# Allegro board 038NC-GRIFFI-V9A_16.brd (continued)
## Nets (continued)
GX1X_3419_17-155: SLOT17.F15
GX1X_3420_17-156: SLOT17.Z15
GX1X_3421_17-157: SLOT17.Z13
GX1X_3422_17-158: SLOT17.A13
GX1X_3423_17-159: SLOT17.B13
GX1X_3424_17-160: SLOT17.C13
GX1X_3425_17-161: SLOT17.D13
GX1X_3426_17-162: SLOT17.E13
GX1X_3427_17-163: SLOT17.F13
GX1X_3428_17-164: SLOT17.A11
GX1X_3429_17-165: SLOT17.B11
GX1X_3430_17-166: SLOT17.C11
GX1X_3431_17-167: SLOT17.D11
GX1X_3432_17-168: SLOT17.E11
GX1X_3433_17-169: SLOT17.F11
GX1X_3434_17-170: SLOT17.Z11
GX1X_3435_17-171: SLOT17.Z9
GX1X_3436_17-172: SLOT17.A9
GX1X_3437_17-173: SLOT17.B9
GX1X_3438_17-174: SLOT17.C9
GX1X_3439_17-175: SLOT17.D9
GX1X_3440_17-176: SLOT17.E9
GX1X_3441_17-177: SLOT17.F9
GX1X_3442_17-178: SLOT17.A7
GX1X_3443_17-179: SLOT17.B7
GX1X_3444_17-180: SLOT17.C7
GX1X_3445_17-181: SLOT17.D7
GX1X_3446_17-182: SLOT17.E7
GX1X_3447_17-183: SLOT17.F7
GX1X_3448_17-184: SLOT17.Z7
GX1X_3449_17-185: SLOT17.Z5
GX1X_3450_17-186: SLOT17.A5
GX1X_3451_17-187: SLOT17.B5
GX1X_3452_17-188: SLOT17.C5
GX1X_3453_17-189: SLOT17.D5
GX1X_3454_17-190: SLOT17.E5
GX1X_3455_17-191: SLOT17.F5
GX1X_3648_19-0: SLOT19.C61
GX1X_3649_19-1: SLOT19.D61
GX1X_3650_19-2: SLOT19.E61
GX1X_3651_19-3: SLOT19.F61
GX1X_3652_19-4: SLOT19.A59
GX1X_3653_19-5: SLOT19.B59
GX1X_3654_19-6: SLOT19.C59
GX1X_3655_19-7: SLOT19.D59
GX1X_3656_19-8: SLOT19.E59
GX1X_3657_19-9: SLOT19.F59
GX1X_3658_19-10: SLOT19.Z59
GX1X_3659_19-11: SLOT19.Z57
GX1X_3660_19-12: SLOT19.A57
GX1X_3661_19-13: SLOT19.B57
GX1X_3662_19-14: SLOT19.C57
GX1X_3663_19-15: SLOT19.D57
GX1X_3664_19-16: SLOT19.E57
GX1X_3665_19-17: SLOT19.F57
GX1X_3666_19-18: SLOT19.A55
GX1X_3667_19-19: SLOT19.B55
GX1X_3668_19-20: SLOT19.C55
GX1X_3669_19-21: SLOT19.D55
GX1X_3670_19-22: SLOT19.E55
GX1X_3671_19-23: SLOT19.F55
GX1X_3672_19-24: SLOT19.Z55
GX1X_3673_19-25: SLOT19.Z53
GX1X_3674_19-26: SLOT19.A53
GX1X_3675_19-27: SLOT19.B53
GX1X_3676_19-28: SLOT19.C53
GX1X_3677_19-29: SLOT19.D53
GX1X_3678_19-30: SLOT19.E53
GX1X_3679_19-31: SLOT19.F53
GX1X_3680_19-32: SLOT19.A51
GX1X_3681_19-33: SLOT19.B51
GX1X_3682_19-34: SLOT19.C51
GX1X_3683_19-35: SLOT19.D51
GX1X_3684_19-36: SLOT19.E51
GX1X_3685_19-37: SLOT19.F51
GX1X_3686_19-38: SLOT19.A49
GX1X_3687_19-39: SLOT19.B49
GX1X_3688_19-40: SLOT19.C49
GX1X_3689_19-41: SLOT19.D49
GX1X_3690_19-42: SLOT19.E49
GX1X_3691_19-43: SLOT19.F49
GX1X_3692_19-44: SLOT19.Z49
GX1X_3693_19-45: SLOT19.Z47
GX1X_3694_19-46: SLOT19.A47
GX1X_3695_19-47: SLOT19.B47
GX1X_3696_19-48: SLOT19.C47
GX1X_3697_19-49: SLOT19.D47
GX1X_3698_19-50: SLOT19.E47
GX1X_3699_19-51: SLOT19.F47
GX1X_3700_19-52: SLOT19.A45
GX1X_3701_19-53: SLOT19.B45
GX1X_3702_19-54: SLOT19.C45
GX1X_3703_19-55: SLOT19.D45
GX1X_3704_19-56: SLOT19.E45
GX1X_3705_19-57: SLOT19.F45
GX1X_3706_19-58: SLOT19.Z45
GX1X_3707_19-59: SLOT19.Z43
GX1X_3708_19-60: SLOT19.A43
GX1X_3709_19-61: SLOT19.B43
GX1X_3710_19-62: SLOT19.C43
GX1X_3711_19-63: SLOT19.D43
GX1X_3712_19-64: SLOT19.A37
GX1X_3713_19-65: SLOT19.B37
GX1X_3714_19-66: SLOT19.C37
GX1X_3715_19-67: SLOT19.D37
GX1X_3716_19-68: SLOT19.E37
GX1X_3717_19-69: SLOT19.F37
GX1X_3718_19-70: SLOT19.A35
GX1X_3719_19-71: SLOT19.B35
GX1X_3720_19-72: SLOT19.C35
GX1X_3721_19-73: SLOT19.D35
GX1X_3722_19-74: SLOT19.E35
GX1X_3723_19-75: SLOT19.F35
GX1X_3724_19-76: SLOT19.Z35
GX1X_3725_19-77: SLOT19.Z33
GX1X_3726_19-78: SLOT19.A33
GX1X_3727_19-79: SLOT19.B33
GX1X_3728_19-80: SLOT19.C33
GX1X_3729_19-81: SLOT19.D33
GX1X_3730_19-82: SLOT19.E33
GX1X_3731_19-83: SLOT19.F33
GX1X_3732_19-84: SLOT19.A31
GX1X_3733_19-85: SLOT19.B31
GX1X_3734_19-86: SLOT19.C31
GX1X_3735_19-87: SLOT19.D31
GX1X_3736_19-88: SLOT19.E31
GX1X_3737_19-89: SLOT19.F31
GX1X_3738_19-90: SLOT19.Z31
GX1X_3739_19-91: SLOT19.Z29
GX1X_3740_19-92: SLOT19.A29
GX1X_3741_19-93: SLOT19.B29
GX1X_3742_19-94: SLOT19.C29
GX1X_3743_19-95: SLOT19.D29
GX1X_3744_19-96: SLOT19.E29
GX1X_3745_19-97: SLOT19.F29
GX1X_3746_19-98: SLOT19.A27
GX1X_3747_19-99: SLOT19.B27
GX1X_3748_19-100: SLOT19.C27
GX1X_3749_19-101: SLOT19.D27
GX1X_3750_19-102: SLOT19.E27
GX1X_3751_19-103: SLOT19.F27
GX1X_3752_19-104: SLOT19.Z27
GX1X_3753_19-105: SLOT19.Z25
GX1X_3754_19-106: SLOT19.A25
GX1X_3755_19-107: SLOT19.B25
GX1X_3756_19-108: SLOT19.C25
GX1X_3757_19-109: SLOT19.D25
GX1X_3758_19-110: SLOT19.E25
GX1X_3759_19-111: SLOT19.F25
GX1X_3760_19-112: SLOT19.A23
GX1X_3761_19-113: SLOT19.B23
GX1X_3762_19-114: SLOT19.C23
GX1X_3763_19-115: SLOT19.D23
GX1X_3764_19-116: SLOT19.E23
GX1X_3765_19-117: SLOT19.F23
GX1X_3766_19-118: SLOT19.Z23
GX1X_3767_19-119: SLOT19.Z21
GX1X_3768_19-120: SLOT19.A21
GX1X_3769_19-121: SLOT19.B21
GX1X_3770_19-122: SLOT19.C21
GX1X_3771_19-123: SLOT19.D21
GX1X_3772_19-124: SLOT19.E21
GX1X_3773_19-125: SLOT19.F21
GX1X_3774_19-126: SLOT19.B19
GX1X_3775_19-127: SLOT19.C19
GX1X_3776_19-128: SLOT19.E43
GX1X_3777_19-129: SLOT19.F43
GX1X_3778_19-130: SLOT19.A41
GX1X_3779_19-131: SLOT19.B41
GX1X_3780_19-132: SLOT19.C41
GX1X_3781_19-133: SLOT19.D41
GX1X_3782_19-134: SLOT19.E41
GX1X_3783_19-135: SLOT19.F41
GX1X_3784_19-136: SLOT19.Z41
GX1X_3785_19-137: SLOT19.Z39
GX1X_3786_19-138: SLOT19.A39
GX1X_3787_19-139: SLOT19.B39
GX1X_3788_19-140: SLOT19.C39
GX1X_3789_19-141: SLOT19.D39
GX1X_3790_19-142: SLOT19.E39
GX1X_3791_19-143: SLOT19.F39
GX1X_3792_19-144: SLOT19.A17
GX1X_3793_19-145: SLOT19.B17
GX1X_3794_19-146: SLOT19.C17
GX1X_3795_19-147: SLOT19.D17
GX1X_3796_19-148: SLOT19.E17
GX1X_3797_19-149: SLOT19.F17
GX1X_3798_19-150: SLOT19.A15
GX1X_3799_19-151: SLOT19.B15
GX1X_3800_19-152: SLOT19.C15
GX1X_3801_19-153: SLOT19.D15
GX1X_3802_19-154: SLOT19.E15
GX1X_3803_19-155: SLOT19.F15
GX1X_3804_19-156: SLOT19.Z15
GX1X_3805_19-157: SLOT19.Z13
GX1X_3806_19-158: SLOT19.A13
GX1X_3807_19-159: SLOT19.B13
GX1X_3808_19-160: SLOT19.C13
GX1X_3809_19-161: SLOT19.D13
GX1X_3810_19-162: SLOT19.E13
GX1X_3811_19-163: SLOT19.F13
GX1X_3812_19-164: SLOT19.A11
GX1X_3813_19-165: SLOT19.B11
GX1X_3814_19-166: SLOT19.C11
GX1X_3815_19-167: SLOT19.D11
GX1X_3816_19-168: SLOT19.E11
GX1X_3817_19-169: SLOT19.F11
GX1X_3818_19-170: SLOT19.Z11
GX1X_3819_19-171: SLOT19.Z9
GX1X_3820_19-172: SLOT19.A9
GX1X_3821_19-173: SLOT19.B9
GX1X_3822_19-174: SLOT19.C9
GX1X_3823_19-175: SLOT19.D9
GX1X_3824_19-176: SLOT19.E9
GX1X_3825_19-177: SLOT19.F9
GX1X_3826_19-178: SLOT19.A7
GX1X_3827_19-179: SLOT19.B7
GX1X_3828_19-180: SLOT19.C7
GX1X_3829_19-181: SLOT19.D7
GX1X_3830_19-182: SLOT19.E7
GX1X_3831_19-183: SLOT19.F7
GX1X_3832_19-184: SLOT19.Z7
GX1X_3833_19-185: SLOT19.Z5
GX1X_3834_19-186: SLOT19.A5
GX1X_3835_19-187: SLOT19.B5
GX1X_3836_19-188: SLOT19.C5
GX1X_3837_19-189: SLOT19.D5
GX1X_3838_19-190: SLOT19.E5
GX1X_3839_19-191: SLOT19.F5
HDVI_721_10-CH1BP: SLOT10.B35
HDVI_721_10-CH1F: SLOT10.F33 SLOT10.F35 UNK8K10.2
HDVI_721_10-CH1GS: SLOT10.A33 SLOT10.A35 UNK8SH9.1
HDVI_721_10-CH1S: SLOT10.C33 SLOT10.C35 UNK8K10.7
HDVI_722_10-CH2BP: SLOT10.B33
HDVI_723_10-CH3BP: SLOT10.B31
HDVI_723_10-CH3F: SITE8.F25(VSYS_F) SLOT10.F29 SLOT10.F31 UNK8CS25.1 UNK8K2.3 UNK8TP_VSYS_F.1
HDVI_723_10-CH3GS: SLOT10.A29 SLOT10.A31 UNK8SH7.2
HDVI_723_10-CH3S: SITE8.S25(VSYS_S) SLOT10.C29 SLOT10.C31 UNK8TP_VSYS_S.1
HDVI_724_10-CH4BP: SLOT10.B29
HDVI_725_10-CH5BP: SLOT10.B27
HDVI_725_10-CH5F: SITE8.F5(LSOUT1 / ILIM1_F) SLOT10.F27 UNK8CS5.2 UNK8K8.3 UNK8SH36.2 UNK8TP_LSOUT1_F.1
HDVI_725_10-CH5GS: SLOT10.A27 UNK8SH32.1
HDVI_725_10-CH5S: SITE8.S5(LSOUT1 / ILIM1_S) SLOT10.C27 UNK8TP_LSOUT1_S.1
HDVI_726_10-CH6BP: SLOT10.B25
HDVI_726_10-CH6F: SLOT10.F25 UNK8K13.4 UNK8TP_NPG/ATB1_F.1
HDVI_726_10-CH6GS: SLOT10.A25 UNK8SH16.1
HDVI_726_10-CH6S: SLOT10.C25 UNK8K13.5 UNK8TP_NPG/ATB1_S.1
HDVI_727_10-CH7BP: SLOT10.B23
HDVI_727_10-CH7F: SLOT10.F23 UNK8K14.4 UNK8TP_NCHG/ATB0_F.1
HDVI_727_10-CH7GS: SLOT10.A23 UNK8SH14.1
HDVI_727_10-CH7S: SLOT10.C23 UNK8K14.5
HDVI_728_10-CH8BP: SLOT10.B21
HDVI_728_10-CH8F: SITE8.F19(LSOUT2 / SUSPEND_F) SLOT10.F21 UNK8CS19.1 UNK8K8.6 UNK8SH38.2 UNK8TP_LSOUT2/SUSPEND_F.1
HDVI_728_10-CH8GS: SLOT10.A21 UNK8SH30.2
HDVI_728_10-CH8S: SITE8.S19(LSOUT2 / SUSPEND_S) SLOT10.C21 UNK8TP_LSOUT2/SUSPEND1_S.1
HDVI_729_10-CH9BP: SLOT10.D37
HDVI_729_10-CH9F: SLOT10.E35 SLOT10.F37 UNK6K10.2
HDVI_729_10-CH9GS: SLOT10.B37 SLOT10.C37 UNK6SH9.1
HDVI_729_10-CH9S: SLOT10.E33 SLOT10.E37 UNK6K10.7
HDVI_730_10-CH10BP: SLOT10.D33
HDVI_731_10-CH11BP: SLOT10.D29
HDVI_731_10-CH11F: SITE6.F25(VSYS_F) SLOT10.E27 SLOT10.E31 UNK6CS25.1 UNK6K2.3 UNK6TP_VSYS_F.1
HDVI_731_10-CH11GS: SLOT10.A37 SLOT10.B19 UNK6SH7.2
HDVI_731_10-CH11S: SITE6.S25(VSYS_S) SLOT10.E25 SLOT10.E29 UNK6TP_VSYS_S.1
HDVI_732_10-CH12BP: SLOT10.D25
HDVI_733_10-CH13BP: SLOT10.D21
HDVI_733_10-CH13F: SITE6.F5(LSOUT1 / ILIM1_F) SLOT10.E23 UNK6CS5.2 UNK6K8.3 UNK6SH36.2 UNK6TP_LSOUT1_F.1
HDVI_733_10-CH13GS: SLOT10.A19 UNK6SH32.1
HDVI_733_10-CH13S: SITE6.S5(LSOUT1 / ILIM1_S) SLOT10.E21 UNK6TP_LSOUT1_S.1
HDVI_734_10-CH14BP: SLOT10.D19
HDVI_734_10-CH14F: SLOT10.F19 UNK6K13.4 UNK6TP_NPG/ATB1_F.1
HDVI_734_10-CH14GS: SLOT10.C19 UNK6SH16.1
HDVI_734_10-CH14S: SLOT10.E19 UNK6K13.5 UNK6TP_NPG/ATB1_S.1
HDVI_735_10-CH15BP: SLOT10.D17
HDVI_735_10-CH15F: SLOT10.F17 UNK6K14.4 UNK6TP_NCHG/ATB0_F.1
HDVI_735_10-CH15GS: SLOT10.A17 UNK6SH14.1
HDVI_735_10-CH15S: SLOT10.E17 UNK6K14.5
HDVI_736_10-CH16BP: SLOT10.C17
HDVI_736_10-CH16F: SITE6.F19(LSOUT2 / SUSPEND_F) SLOT10.E15 UNK6CS19.1 UNK6K8.6 UNK6SH38.2 UNK6TP_LSOUT2/SUSPEND_F.1
HDVI_736_10-CH16GS: SLOT10.B17 UNK6SH30.2
HDVI_736_10-CH16S: SITE6.S19(LSOUT2 / SUSPEND_S) SLOT10.D15 UNK6TP_LSOUT2/SUSPEND1_S.1
HDVI_737_10-CH17BP: SLOT10.B15
HDVI_737_10-CH17F: SLOT10.F13 SLOT10.F15 UNK2K10.2
HDVI_737_10-CH17GS: SLOT10.A13 SLOT10.A15 UNK2SH9.1
HDVI_737_10-CH17S: SLOT10.C15 SLOT10.E13 UNK2K10.7
HDVI_738_10-CH18BP: SLOT10.D13
HDVI_739_10-CH19BP: SLOT10.D11
HDVI_739_10-CH19F: SITE2.F25(VSYS_F) SLOT10.E9 SLOT10.F11 UNK2CS25.1 UNK2K2.3 UNK2TP_VSYS_F.1
HDVI_739_10-CH19GS: SLOT10.B13 SLOT10.C13 UNK2SH7.2
HDVI_739_10-CH19S: SITE2.S25(VSYS_S) SLOT10.D9 SLOT10.E11 UNK2TP_VSYS_S.1
HDVI_740_10-CH20BP: SLOT10.C11
HDVI_741_10-CH21BP: SLOT10.B9
HDVI_741_10-CH21F: SITE2.F5(LSOUT1 / ILIM1_F) SLOT10.F9 UNK2CS5.2 UNK2K8.3 UNK2SH36.2 UNK2TP_LSOUT1_F.1
HDVI_741_10-CH21GS: SLOT10.B11 UNK2SH32.1
HDVI_741_10-CH21S: SITE2.S5(LSOUT1 / ILIM1_S) SLOT10.C9 UNK2TP_LSOUT1_S.1
HDVI_742_10-CH22BP: SLOT10.D7
HDVI_742_10-CH22F: SLOT10.F7 UNK2K13.4 UNK2TP_NPG/ATB1_F.1
HDVI_742_10-CH22GS: SLOT10.A11 UNK2SH16.1
HDVI_742_10-CH22S: SLOT10.E7 UNK2K13.5 UNK2TP_NPG/ATB1_S.1
HDVI_743_10-CH23BP: SLOT10.D5
HDVI_743_10-CH23F: SLOT10.F5 UNK2K14.4 UNK2TP_NCHG/ATB0_F.1
HDVI_743_10-CH23GS: SLOT10.A9 UNK2SH14.1
HDVI_743_10-CH23S: SLOT10.E5 UNK2K14.5
HDVI_744_10-CH24BP: SLOT10.D3
HDVI_744_10-CH24F: SITE2.F19(LSOUT2 / SUSPEND_F) SLOT10.F3 UNK2CS19.1 UNK2K8.6 UNK2SH38.2 UNK2TP_LSOUT2/SUSPEND_F.1
HDVI_744_10-CH24GS: SLOT10.A7 UNK2SH30.2
HDVI_744_10-CH24S: SITE2.S19(LSOUT2 / SUSPEND_S) SLOT10.E3 UNK2TP_LSOUT2/SUSPEND1_S.1
HDVI_745_10-CH25BP: SLOT10.D1
HDVI_745_10-CH25F: SLOT10.F1
HDVI_745_10-CH25GS: SLOT10.B7
HDVI_745_10-CH25S: SLOT10.E1
HDVI_746_10-CH26BP: SLOT10.C3
HDVI_746_10-CH26F: SLOT10.G4
HDVI_746_10-CH26GS: SLOT10.C7
HDVI_746_10-CH26S: SLOT10.C1
HDVI_747_10-CH27BP: SLOT10.D2
HDVI_747_10-CH27F: SLOT10.F2
HDVI_747_10-CH27GS: SLOT10.C5
HDVI_747_10-CH27S: SLOT10.C4
HDVI_748_10-CH28BP: SLOT10.B3
HDVI_748_10-CH28F: SLOT10.A4
HDVI_748_10-CH28GS: SLOT10.B5
HDVI_748_10-CH28S: SLOT10.B1
HDVI_749_10-CH29BP: SLOT10.A3
HDVI_749_10-CH29F: SLOT10.B2
HDVI_749_10-CH29GS: SLOT10.A5
HDVI_749_10-CH29S: SLOT10.A1
HDVI_750_10-CH30BP: SLOT10.A60
HDVI_750_10-CH30F: SLOT10.B62
HDVI_750_10-CH30GS: SLOT10.B58
HDVI_750_10-CH30S: SLOT10.A61
HDVI_751_10-CH31BP: SLOT10.A59
HDVI_751_10-CH31F: SLOT10.C62
HDVI_751_10-CH31GS: SLOT10.A57
HDVI_751_10-CH31S: SLOT10.B61
HDVI_752_10-CH32BP: SLOT10.E60
HDVI_752_10-CH32F: SLOT10.F62
HDVI_752_10-CH32GS: SLOT10.C60
HDVI_752_10-CH32S: SLOT10.F61
HDVI_753_10-CH33BP: SLOT10.D61
HDVI_753_10-CH33F: SLOT10.E62 SLOT10.F59 UNK16K10.2
HDVI_753_10-CH33GS: SLOT10.B59 SLOT10.C61 UNK16SH9.1
HDVI_753_10-CH33S: SLOT10.D59 SLOT10.E61 UNK16K10.7
HDVI_754_10-CH34BP: SLOT10.C59
HDVI_755_10-CH35BP: SLOT10.F58
HDVI_755_10-CH35F: SITE16.F25(VSYS_F) SLOT10.E57 SLOT10.G60 UNK16CS25.1 UNK16K2.3 UNK16TP_VSYS_F.1
HDVI_755_10-CH35GS: SLOT10.B57 SLOT10.D58 UNK16SH7.2
HDVI_755_10-CH35S: SITE16.S25(VSYS_S) SLOT10.D57 SLOT10.E59 UNK16TP_VSYS_S.1
HDVI_756_10-CH36BP: SLOT10.C57
HDVI_757_10-CH37BP: SLOT10.E56
HDVI_757_10-CH37F: SITE16.F5(LSOUT1 / ILIM1_F) SLOT10.F57 UNK16CS5.2 UNK16K8.3 UNK16SH36.2 UNK16TP_LSOUT1_F.1
HDVI_757_10-CH37GS: SLOT10.C56 UNK16SH32.1
HDVI_757_10-CH37S: SITE16.S5(LSOUT1 / ILIM1_S) SLOT10.G56 UNK16TP_LSOUT1_S.1
HDVI_758_10-CH38BP: SLOT10.D55
HDVI_758_10-CH38F: SLOT10.F55 UNK16K13.4 UNK16TP_NPG/ATB1_F.1
HDVI_758_10-CH38GS: SLOT10.B55 UNK16SH16.1
HDVI_758_10-CH38S: SLOT10.E55 UNK16K13.5 UNK16TP_NPG/ATB1_S.1
HDVI_759_10-CH39BP: SLOT10.B54
HDVI_759_10-CH39F: SLOT10.E52 UNK16K14.4 UNK16TP_NCHG/ATB0_F.1
HDVI_759_10-CH39GS: SLOT10.A55 UNK16SH14.1
HDVI_759_10-CH39S: SLOT10.C55 UNK16K14.5
HDVI_760_10-CH40BP: SLOT10.D54
HDVI_760_10-CH40F: SITE16.F19(LSOUT2 / SUSPEND_F) SLOT10.G52 UNK16CS19.1 UNK16K8.6 UNK16SH38.2 UNK16TP_LSOUT2/SUSPEND_F.1
HDVI_760_10-CH40GS: SLOT10.A56 UNK16SH30.2
HDVI_760_10-CH40S: SITE16.S19(LSOUT2 / SUSPEND_S) SLOT10.F54 UNK16TP_LSOUT2/SUSPEND1_S.1
HDVI_761_10-CH41BP: SLOT10.B53
HDVI_761_10-CH41F: SLOT10.F51 SLOT10.F53 UNK14K10.2
HDVI_761_10-CH41GS: SLOT10.A52 SLOT10.A53 UNK14SH9.1
HDVI_761_10-CH41S: SLOT10.C53 SLOT10.E53 UNK14K10.7
HDVI_762_10-CH42BP: SLOT10.D53
HDVI_763_10-CH43BP: SLOT10.C51
HDVI_763_10-CH43F: SITE14.F25(VSYS_F) SLOT10.E51 SLOT10.F49 UNK14CS25.1 UNK14K2.3 UNK14TP_VSYS_F.1
HDVI_763_10-CH43GS: SLOT10.A51 SLOT10.C52 UNK14SH7.2
HDVI_763_10-CH43S: SITE14.S25(VSYS_S) SLOT10.D51 SLOT10.F50 UNK14TP_VSYS_S.1
HDVI_764_10-CH44BP: SLOT10.D50
HDVI_765_10-CH45BP: SLOT10.B50
HDVI_765_10-CH45F: SITE14.F5(LSOUT1 / ILIM1_F) SLOT10.E49 UNK14CS5.2 UNK14K8.3 UNK14SH36.2 UNK14TP_LSOUT1_F.1
HDVI_765_10-CH45GS: SLOT10.B51 UNK14SH32.1
HDVI_765_10-CH45S: SITE14.S5(LSOUT1 / ILIM1_S) SLOT10.D49 UNK14TP_LSOUT1_S.1
HDVI_766_10-CH46BP: SLOT10.B49
HDVI_766_10-CH46F: SLOT10.G48 UNK14K13.4 UNK14TP_NPG/ATB1_F.1
HDVI_766_10-CH46GS: SLOT10.A49 UNK14SH16.1
HDVI_766_10-CH46S: SLOT10.C49 UNK14K13.5 UNK14TP_NPG/ATB1_S.1
HDVI_767_10-CH47BP: SLOT10.D47
HDVI_767_10-CH47F: SLOT10.F47 UNK14K14.4 UNK14TP_NCHG/ATB0_F.1
HDVI_767_10-CH47GS: SLOT10.A48 UNK14SH14.1
HDVI_767_10-CH47S: SLOT10.E47 UNK14K14.5
HDVI_768_10-CH48BP: SLOT10.C45
HDVI_768_10-CH48F: SITE14.F19(LSOUT2 / SUSPEND_F) SLOT10.F45 UNK14CS19.1 UNK14K8.6 UNK14SH38.2 UNK14TP_LSOUT2/SUSPEND_F.1
HDVI_768_10-CH48GS: SLOT10.C48 UNK14SH30.2
HDVI_768_10-CH48S: SITE14.S19(LSOUT2 / SUSPEND_S) SLOT10.D46 UNK14TP_LSOUT2/SUSPEND1_S.1
HDVI_769_10-CH49BP: SLOT10.C47
HDVI_769_10-CH49F: SLOT10.F46 SLOT10.G44 UNK12K10.2
HDVI_769_10-CH49GS: SLOT10.B47 SLOT10.E48 UNK12SH9.1
HDVI_769_10-CH49S: SLOT10.B45 SLOT10.E45 UNK12K10.7
HDVI_770_10-CH50BP: SLOT10.B46
HDVI_771_10-CH51BP: SLOT10.D45
HDVI_771_10-CH51F: SITE12.F25(VSYS_F) SLOT10.F41 SLOT10.F43 UNK12CS25.1 UNK12K2.3 UNK12TP_VSYS_F.1
HDVI_771_10-CH51GS: SLOT10.A45 SLOT10.A47 UNK12SH7.2
HDVI_771_10-CH51S: SITE12.S25(VSYS_S) SLOT10.E43 SLOT10.F42 UNK12TP_VSYS_S.1
HDVI_772_10-CH52BP: SLOT10.D43
HDVI_773_10-CH53BP: SLOT10.D42
HDVI_773_10-CH53F: SITE12.F5(LSOUT1 / ILIM1_F) SLOT10.G40 UNK12CS5.2 UNK12K8.3 UNK12SH36.2 UNK12TP_LSOUT1_F.1
HDVI_773_10-CH53GS: SLOT10.A44 UNK12SH32.1
HDVI_773_10-CH53S: SITE12.S5(LSOUT1 / ILIM1_S) SLOT10.E41 UNK12TP_LSOUT1_S.1
HDVI_774_10-CH54BP: SLOT10.C41
HDVI_774_10-CH54F: SLOT10.F39 UNK12K13.4 UNK12TP_NPG/ATB1_F.1
HDVI_774_10-CH54GS: SLOT10.C44 UNK12SH16.1
HDVI_774_10-CH54S: SLOT10.D41 UNK12K13.5 UNK12TP_NPG/ATB1_S.1
HDVI_775_10-CH55BP: SLOT10.B41
HDVI_775_10-CH55F: SLOT10.F38 UNK12K14.4 UNK12TP_NCHG/ATB0_F.1
HDVI_775_10-CH55GS: SLOT10.E44 UNK12SH14.1
HDVI_775_10-CH55S: SLOT10.B39 UNK12K14.5
HDVI_776_10-CH56BP: SLOT10.C39
HDVI_776_10-CH56F: SITE12.F19(LSOUT2 / SUSPEND_F) SLOT10.E39 UNK12CS19.1 UNK12K8.6 UNK12SH38.2 UNK12TP_LSOUT2/SUSPEND_F.1
HDVI_776_10-CH56GS: SLOT10.C43 UNK12SH30.2
HDVI_776_10-CH56S: SITE12.S19(LSOUT2 / SUSPEND_S) SLOT10.D39 UNK12TP_LSOUT2/SUSPEND1_S.1
HDVI_777_10-CH57BP: SLOT10.A41
HDVI_777_10-CH57F: SLOT10.C40 SLOT10.E40 UNK10K10.2
HDVI_777_10-CH57GS: SLOT10.A43 SLOT10.B43 UNK10SH9.1
HDVI_777_10-CH57S: SLOT10.A39 SLOT10.A40 UNK10K10.7
HDVI_778_10-CH58BP: SLOT10.B42
HDVI_779_10-CH59BP: SLOT10.C36
HDVI_779_10-CH59F: SITE10.F25(VSYS_F) SLOT10.G32 SLOT10.G36 UNK10CS25.1 UNK10K2.3 UNK10TP_VSYS_F.1
HDVI_779_10-CH59GS: SLOT10.B38 SLOT10.D38 UNK10SH7.2
HDVI_779_10-CH59S: SITE10.S25(VSYS_S) SLOT10.E32 SLOT10.E36 UNK10TP_VSYS_S.1
HDVI_780_10-CH60BP: SLOT10.D34
HDVI_781_10-CH61BP: SLOT10.E24
HDVI_781_10-CH61F: SITE10.F5(LSOUT1 / ILIM1_F) SLOT10.E28 UNK10CS5.2 UNK10K8.3 UNK10SH36.2 UNK10TP_LSOUT1_F.1
HDVI_781_10-CH61GS: SLOT10.A36 UNK10SH32.1
HDVI_781_10-CH61S: SITE10.S5(LSOUT1 / ILIM1_S) SLOT10.F26 UNK10TP_LSOUT1_S.1
HDVI_782_10-CH62BP: SLOT10.F18
HDVI_782_10-CH62F: SLOT10.G20 UNK10K13.4 UNK10TP_NPG/ATB1_F.1
HDVI_782_10-CH62GS: SLOT10.B10 UNK10SH16.1
HDVI_782_10-CH62S: SLOT10.E16 UNK10K13.5 UNK10TP_NPG/ATB1_S.1
HDVI_783_10-CH63BP: SLOT10.E12
HDVI_783_10-CH63F: SLOT10.F14 UNK10K14.4 UNK10TP_NCHG/ATB0_F.1
HDVI_783_10-CH63GS: SLOT10.A8 UNK10SH14.1
HDVI_783_10-CH63S: SLOT10.D10 UNK10K14.5
HDVI_784_10-CH64BP: SLOT10.E8
HDVI_784_10-CH64F: SITE10.F19(LSOUT2 / SUSPEND_F) SLOT10.G8 UNK10CS19.1 UNK10K8.6 UNK10SH38.2 UNK10TP_LSOUT2/SUSPEND_F.1
HDVI_784_10-CH64GS: SLOT10.C8 UNK10SH30.2
HDVI_784_10-CH64S: SITE10.S19(LSOUT2 / SUSPEND_S) SLOT10.F6 UNK10TP_LSOUT2/SUSPEND1_S.1
HDVI_785_10-CH65BP: SLOT10.B34
HDVI_785_10-CH65F: SLOT10.F30 SLOT10.F34 UNK4K10.2
HDVI_785_10-CH65GS: SLOT10.A32 SLOT10.B30 UNK4SH9.1
HDVI_785_10-CH65S: SLOT10.C28 SLOT10.C32 UNK4K10.7
HDVI_786_10-CH66BP: SLOT10.D30
HDVI_787_10-CH67BP: SLOT10.B26
HDVI_787_10-CH67F: SITE4.F25(VSYS_F) SLOT10.G24 SLOT10.G28 UNK4CS25.1 UNK4K2.3 UNK4TP_VSYS_F.1
HDVI_787_10-CH67GS: SLOT10.A24 SLOT10.A28 UNK4SH7.2
HDVI_787_10-CH67S: SITE4.S25(VSYS_S) SLOT10.B22 SLOT10.D26 UNK4TP_VSYS_S.1
HDVI_788_10-CH68BP: SLOT10.C24
HDVI_789_10-CH69BP: SLOT10.C20
HDVI_789_10-CH69F: SITE4.F5(LSOUT1 / ILIM1_F) SLOT10.F22 UNK4CS5.2 UNK4K8.3 UNK4SH36.2 UNK4TP_LSOUT1_F.1
HDVI_789_10-CH69GS: SLOT10.A20 UNK4SH32.1
HDVI_789_10-CH69S: SITE4.S5(LSOUT1 / ILIM1_S) SLOT10.D22 UNK4TP_LSOUT1_S.1
HDVI_790_10-CH70BP: SLOT10.D18
HDVI_790_10-CH70F: SLOT10.G16 UNK4K13.4 UNK4TP_NPG/ATB1_F.1
HDVI_790_10-CH70GS: SLOT10.B18 UNK4SH16.1
HDVI_790_10-CH70S: SLOT10.E20 UNK4K13.5 UNK4TP_NPG/ATB1_S.1
HDVI_791_10-CH71BP: SLOT10.C16
HDVI_791_10-CH71F: SLOT10.G12 UNK4K14.4 UNK4TP_NCHG/ATB0_F.1
HDVI_791_10-CH71GS: SLOT10.A16 UNK4SH14.1
HDVI_791_10-CH71S: SLOT10.B14 UNK4K14.5
HDVI_792_10-CH72BP: SLOT10.C12
HDVI_792_10-CH72F: SITE4.F19(LSOUT2 / SUSPEND_F) SLOT10.F10 UNK4CS19.1 UNK4K8.6 UNK4SH38.2 UNK4TP_LSOUT2/SUSPEND_F.1
HDVI_792_10-CH72GS: SLOT10.A12 UNK4SH30.2
HDVI_792_10-CH72S: SITE4.S19(LSOUT2 / SUSPEND_S) SLOT10.D14 UNK4TP_LSOUT2/SUSPEND1_S.1
HDVI_937_13-CH1BP: SLOT13.B35
HDVI_937_13-CH1F: SLOT13.F33 SLOT13.F35 UNK9K10.2
HDVI_937_13-CH1GS: SLOT13.A33 SLOT13.A35 UNK9SH9.1
HDVI_937_13-CH1S: SLOT13.C33 SLOT13.C35 UNK9K10.7
HDVI_938_13-CH2BP: SLOT13.B33
HDVI_939_13-CH3BP: SLOT13.B31
HDVI_939_13-CH3F: SITE9.F25(VSYS_F) SLOT13.F29 SLOT13.F31 UNK9CS25.1 UNK9K2.3 UNK9TP_VSYS_F.1
HDVI_939_13-CH3GS: SLOT13.A29 SLOT13.A31 UNK9SH7.2
HDVI_939_13-CH3S: SITE9.S25(VSYS_S) SLOT13.C29 SLOT13.C31 UNK9TP_VSYS_S.1
HDVI_940_13-CH4BP: SLOT13.B29
HDVI_941_13-CH5BP: SLOT13.B27
HDVI_941_13-CH5F: SITE9.F5(LSOUT1 / ILIM1_F) SLOT13.F27 UNK9CS5.2 UNK9K8.3 UNK9SH36.2 UNK9TP_LSOUT1_F.1
HDVI_941_13-CH5GS: SLOT13.A27 UNK9SH32.1
HDVI_941_13-CH5S: SITE9.S5(LSOUT1 / ILIM1_S) SLOT13.C27 UNK9TP_LSOUT1_S.1
HDVI_942_13-CH6BP: SLOT13.B25
HDVI_942_13-CH6F: SLOT13.F25 UNK9K13.4 UNK9TP_NPG/ATB1_F.1
HDVI_942_13-CH6GS: SLOT13.A25 UNK9SH16.1
HDVI_942_13-CH6S: SLOT13.C25 UNK9K13.5 UNK9TP_NPG/ATB1_S.1
HDVI_943_13-CH7BP: SLOT13.B23
HDVI_943_13-CH7F: SLOT13.F23 UNK9K14.4 UNK9TP_NCHG/ATB0_F.1
HDVI_943_13-CH7GS: SLOT13.A23 UNK9SH14.1
HDVI_943_13-CH7S: SLOT13.C23 UNK9K14.5
HDVI_944_13-CH8BP: SLOT13.B21
HDVI_944_13-CH8F: SITE9.F19(LSOUT2 / SUSPEND_F) SLOT13.F21 UNK9CS19.1 UNK9K8.6 UNK9SH38.2 UNK9TP_LSOUT2/SUSPEND_F.1
HDVI_944_13-CH8GS: SLOT13.A21 UNK9SH30.2
HDVI_944_13-CH8S: SITE9.S19(LSOUT2 / SUSPEND_S) SLOT13.C21 UNK9TP_LSOUT2/SUSPEND1_S.1
HDVI_945_13-CH9BP: SLOT13.D37
HDVI_945_13-CH9F: SLOT13.E35 SLOT13.F37 UNK11K10.2
HDVI_945_13-CH9GS: SLOT13.B37 SLOT13.C37 UNK11SH9.1
HDVI_945_13-CH9S: SLOT13.E33 SLOT13.E37 UNK11K10.7
HDVI_946_13-CH10BP: SLOT13.D33
HDVI_947_13-CH11BP: SLOT13.D29
HDVI_947_13-CH11F: SITE11.F25(VSYS_F) SLOT13.E27 SLOT13.E31 UNK11CS25.1 UNK11K2.3 UNK11TP_VSYS_F.1
HDVI_947_13-CH11GS: SLOT13.A37 SLOT13.B19 UNK11SH7.2
HDVI_947_13-CH11S: SITE11.S25(VSYS_S) SLOT13.E25 SLOT13.E29 UNK11TP_VSYS_S.1
HDVI_948_13-CH12BP: SLOT13.D25
HDVI_949_13-CH13BP: SLOT13.D21
HDVI_949_13-CH13F: SITE11.F5(LSOUT1 / ILIM1_F) SLOT13.E23 UNK11CS5.2 UNK11K8.3 UNK11SH36.2 UNK11TP_LSOUT1_F.1
HDVI_949_13-CH13GS: SLOT13.A19 UNK11SH32.1
HDVI_949_13-CH13S: SITE11.S5(LSOUT1 / ILIM1_S) SLOT13.E21 UNK11TP_LSOUT1_S.1
HDVI_950_13-CH14BP: SLOT13.D19
HDVI_950_13-CH14F: SLOT13.F19 UNK11K13.4 UNK11TP_NPG/ATB1_F.1
HDVI_950_13-CH14GS: SLOT13.C19 UNK11SH16.1
HDVI_950_13-CH14S: SLOT13.E19 UNK11K13.5 UNK11TP_NPG/ATB1_S.1
HDVI_951_13-CH15BP: SLOT13.D17
HDVI_951_13-CH15F: SLOT13.F17 UNK11K14.4 UNK11TP_NCHG/ATB0_F.1
HDVI_951_13-CH15GS: SLOT13.A17 UNK11SH14.1
HDVI_951_13-CH15S: SLOT13.E17 UNK11K14.5
HDVI_952_13-CH16BP: SLOT13.C17
HDVI_952_13-CH16F: SITE11.F19(LSOUT2 / SUSPEND_F) SLOT13.E15 UNK11CS19.1 UNK11K8.6 UNK11SH38.2 UNK11TP_LSOUT2/SUSPEND_F.1
HDVI_952_13-CH16GS: SLOT13.B17 UNK11SH30.2
HDVI_952_13-CH16S: SITE11.S19(LSOUT2 / SUSPEND_S) SLOT13.D15 UNK11TP_LSOUT2/SUSPEND1_S.1
HDVI_953_13-CH17BP: SLOT13.B15
HDVI_953_13-CH17F: SLOT13.F13 SLOT13.F15 UNK15K10.2
HDVI_953_13-CH17GS: SLOT13.A13 SLOT13.A15 UNK15SH9.1
HDVI_953_13-CH17S: SLOT13.C15 SLOT13.E13 UNK15K10.7
HDVI_954_13-CH18BP: SLOT13.D13
HDVI_955_13-CH19BP: SLOT13.D11
HDVI_955_13-CH19F: SITE15.F25(VSYS_F) SLOT13.E9 SLOT13.F11 UNK15CS25.1 UNK15K2.3 UNK15TP_VSYS_F.1
HDVI_955_13-CH19GS: SLOT13.B13 SLOT13.C13 UNK15SH7.2
HDVI_955_13-CH19S: SITE15.S25(VSYS_S) SLOT13.D9 SLOT13.E11 UNK15TP_VSYS_S.1
HDVI_956_13-CH20BP: SLOT13.C11
HDVI_957_13-CH21BP: SLOT13.B9
HDVI_957_13-CH21F: SITE15.F5(LSOUT1 / ILIM1_F) SLOT13.F9 UNK15CS5.2 UNK15K8.3 UNK15SH36.2 UNK15TP_LSOUT1_F.1
HDVI_957_13-CH21GS: SLOT13.B11 UNK15SH32.1
HDVI_957_13-CH21S: SITE15.S5(LSOUT1 / ILIM1_S) SLOT13.C9 UNK15TP_LSOUT1_S.1
HDVI_958_13-CH22BP: SLOT13.D7
HDVI_958_13-CH22F: SLOT13.F7 UNK15K13.4 UNK15TP_NPG/ATB1_F.1
HDVI_958_13-CH22GS: SLOT13.A11 UNK15SH16.1
HDVI_958_13-CH22S: SLOT13.E7 UNK15K13.5 UNK15TP_NPG/ATB1_S.1
HDVI_959_13-CH23BP: SLOT13.D5
HDVI_959_13-CH23F: SLOT13.F5 UNK15K14.4 UNK15TP_NCHG/ATB0_F.1
HDVI_959_13-CH23GS: SLOT13.A9 UNK15SH14.1
HDVI_959_13-CH23S: SLOT13.E5 UNK15K14.5
HDVI_960_13-CH24BP: SLOT13.D3
HDVI_960_13-CH24F: SITE15.F19(LSOUT2 / SUSPEND_F) SLOT13.F3 UNK15CS19.1 UNK15K8.6 UNK15SH38.2 UNK15TP_LSOUT2/SUSPEND_F.1
HDVI_960_13-CH24GS: SLOT13.A7 UNK15SH30.2
HDVI_960_13-CH24S: SITE15.S19(LSOUT2 / SUSPEND_S) SLOT13.E3 UNK15TP_LSOUT2/SUSPEND1_S.1
HDVI_961_13-CH25BP: SLOT13.D1
HDVI_961_13-CH25F: SLOT13.F1
HDVI_961_13-CH25GS: SLOT13.B7
HDVI_961_13-CH25S: SLOT13.E1
HDVI_962_13-CH26BP: SLOT13.C3
HDVI_962_13-CH26F: SLOT13.G4
HDVI_962_13-CH26GS: SLOT13.C7
HDVI_962_13-CH26S: SLOT13.C1
HDVI_963_13-CH27BP: SLOT13.D2
HDVI_963_13-CH27F: SLOT13.F2
HDVI_963_13-CH27GS: SLOT13.C5
HDVI_963_13-CH27S: SLOT13.C4
HDVI_964_13-CH28BP: SLOT13.B3
HDVI_964_13-CH28F: SLOT13.A4
HDVI_964_13-CH28GS: SLOT13.B5
HDVI_964_13-CH28S: SLOT13.B1
HDVI_965_13-CH29BP: SLOT13.A3
HDVI_965_13-CH29F: SLOT13.B2
HDVI_965_13-CH29GS: SLOT13.A5
HDVI_965_13-CH29S: SLOT13.A1
HDVI_966_13-CH30BP: SLOT13.A60
HDVI_966_13-CH30F: SLOT13.B62
HDVI_966_13-CH30GS: SLOT13.B58
HDVI_966_13-CH30S: SLOT13.A61
HDVI_967_13-CH31BP: SLOT13.A59
HDVI_967_13-CH31F: SLOT13.C62
HDVI_967_13-CH31GS: SLOT13.A57
HDVI_967_13-CH31S: SLOT13.B61
HDVI_968_13-CH32BP: SLOT13.E60
HDVI_968_13-CH32F: SLOT13.F62
HDVI_968_13-CH32GS: SLOT13.C60
HDVI_968_13-CH32S: SLOT13.F61
HDVI_969_13-CH33BP: SLOT13.D61
HDVI_969_13-CH33F: SLOT13.E62 SLOT13.F59 UNK1K10.2
HDVI_969_13-CH33GS: SLOT13.B59 SLOT13.C61 UNK1SH9.1
HDVI_969_13-CH33S: SLOT13.D59 SLOT13.E61 UNK1K10.7
HDVI_970_13-CH34BP: SLOT13.C59
HDVI_971_13-CH35BP: SLOT13.F58
HDVI_971_13-CH35F: SITE1.F25(VSYS_F) SLOT13.E57 SLOT13.G60 UNK1CS25.1 UNK1K2.3 UNK1TP_VSYS_F.1
HDVI_971_13-CH35GS: SLOT13.B57 SLOT13.D58 UNK1SH7.2
HDVI_971_13-CH35S: SITE1.S25(VSYS_S) SLOT13.D57 SLOT13.E59 UNK1TP_VSYS_S.1
HDVI_972_13-CH36BP: SLOT13.C57
HDVI_973_13-CH37BP: SLOT13.E56
HDVI_973_13-CH37F: SITE1.F5(LSOUT1 / ILIM1_F) SLOT13.F57 UNK1CS5.2 UNK1K8.3 UNK1SH36.2 UNK1TP_LSOUT1_F.1
HDVI_973_13-CH37GS: SLOT13.C56 UNK1SH32.1
HDVI_973_13-CH37S: SITE1.S5(LSOUT1 / ILIM1_S) SLOT13.G56 UNK1TP_LSOUT1_S.1
HDVI_974_13-CH38BP: SLOT13.D55
HDVI_974_13-CH38F: SLOT13.F55 UNK1K13.4 UNK1TP_NPG/ATB1_F.1
HDVI_974_13-CH38GS: SLOT13.B55 UNK1SH16.1
HDVI_974_13-CH38S: SLOT13.E55 UNK1K13.5 UNK1TP_NPG/ATB1_S.1
HDVI_975_13-CH39BP: SLOT13.B54
HDVI_975_13-CH39F: SLOT13.E52 UNK1K14.4 UNK1TP_NCHG/ATB0_F.1
HDVI_975_13-CH39GS: SLOT13.A55 UNK1SH14.1
HDVI_975_13-CH39S: SLOT13.C55 UNK1K14.5
HDVI_976_13-CH40BP: SLOT13.D54
HDVI_976_13-CH40F: SITE1.F19(LSOUT2 / SUSPEND_F) SLOT13.G52 UNK1CS19.1 UNK1K8.6 UNK1SH38.2 UNK1TP_LSOUT2/SUSPEND_F.1
HDVI_976_13-CH40GS: SLOT13.A56 UNK1SH30.2
HDVI_976_13-CH40S: SITE1.S19(LSOUT2 / SUSPEND_S) SLOT13.F54 UNK1TP_LSOUT2/SUSPEND1_S.1
HDVI_977_13-CH41BP: SLOT13.B53
HDVI_977_13-CH41F: SLOT13.F51 SLOT13.F53 UNK3K10.2
HDVI_977_13-CH41GS: SLOT13.A52 SLOT13.A53 UNK3SH9.1
HDVI_977_13-CH41S: SLOT13.C53 SLOT13.E53 UNK3K10.7
HDVI_978_13-CH42BP: SLOT13.D53
HDVI_979_13-CH43BP: SLOT13.C51
HDVI_979_13-CH43F: SITE3.F25(VSYS_F) SLOT13.E51 SLOT13.F49 UNK3CS25.1 UNK3K2.3 UNK3TP_VSYS_F.1
HDVI_979_13-CH43GS: SLOT13.A51 SLOT13.C52 UNK3SH7.2
HDVI_979_13-CH43S: SITE3.S25(VSYS_S) SLOT13.D51 SLOT13.F50 UNK3TP_VSYS_S.1
HDVI_980_13-CH44BP: SLOT13.D50
HDVI_981_13-CH45BP: SLOT13.B50
HDVI_981_13-CH45F: SITE3.F5(LSOUT1 / ILIM1_F) SLOT13.E49 UNK3CS5.2 UNK3K8.3 UNK3SH36.2 UNK3TP_LSOUT1_F.1
HDVI_981_13-CH45GS: SLOT13.B51 UNK3SH32.1
HDVI_981_13-CH45S: SITE3.S5(LSOUT1 / ILIM1_S) SLOT13.D49 UNK3TP_LSOUT1_S.1
HDVI_982_13-CH46BP: SLOT13.B49
HDVI_982_13-CH46F: SLOT13.G48 UNK3K13.4 UNK3TP_NPG/ATB1_F.1
HDVI_982_13-CH46GS: SLOT13.A49 UNK3SH16.1
HDVI_982_13-CH46S: SLOT13.C49 UNK3K13.5 UNK3TP_NPG/ATB1_S.1
HDVI_983_13-CH47BP: SLOT13.D47
HDVI_983_13-CH47F: SLOT13.F47 UNK3K14.4 UNK3TP_NCHG/ATB0_F.1
HDVI_983_13-CH47GS: SLOT13.A48 UNK3SH14.1
HDVI_983_13-CH47S: SLOT13.E47 UNK3K14.5
HDVI_984_13-CH48BP: SLOT13.C45
HDVI_984_13-CH48F: SITE3.F19(LSOUT2 / SUSPEND_F) SLOT13.F45 UNK3CS19.1 UNK3K8.6 UNK3SH38.2 UNK3TP_LSOUT2/SUSPEND_F.1
HDVI_984_13-CH48GS: SLOT13.C48 UNK3SH30.2
HDVI_984_13-CH48S: SITE3.S19(LSOUT2 / SUSPEND_S) SLOT13.D46 UNK3TP_LSOUT2/SUSPEND1_S.1
HDVI_985_13-CH49BP: SLOT13.C47
HDVI_985_13-CH49F: SLOT13.F46 SLOT13.G44 UNK5K10.2
HDVI_985_13-CH49GS: SLOT13.B47 SLOT13.E48 UNK5SH9.1
HDVI_985_13-CH49S: SLOT13.B45 SLOT13.E45 UNK5K10.7
HDVI_986_13-CH50BP: SLOT13.B46
HDVI_987_13-CH51BP: SLOT13.D45
HDVI_987_13-CH51F: SITE5.F25(VSYS_F) SLOT13.F41 SLOT13.F43 UNK5CS25.1 UNK5K2.3 UNK5TP_VSYS_F.1
HDVI_987_13-CH51GS: SLOT13.A45 SLOT13.A47 UNK5SH7.2
HDVI_987_13-CH51S: SITE5.S25(VSYS_S) SLOT13.E43 SLOT13.F42 UNK5TP_VSYS_S.1
HDVI_988_13-CH52BP: SLOT13.D43
HDVI_989_13-CH53BP: SLOT13.D42
HDVI_989_13-CH53F: SITE5.F5(LSOUT1 / ILIM1_F) SLOT13.G40 UNK5CS5.2 UNK5K8.3 UNK5SH36.2 UNK5TP_LSOUT1_F.1
HDVI_989_13-CH53GS: SLOT13.A44 UNK5SH32.1
HDVI_989_13-CH53S: SITE5.S5(LSOUT1 / ILIM1_S) SLOT13.E41 UNK5TP_LSOUT1_S.1
HDVI_990_13-CH54BP: SLOT13.C41
HDVI_990_13-CH54F: SLOT13.F39 UNK5K13.4 UNK5TP_NPG/ATB1_F.1
HDVI_990_13-CH54GS: SLOT13.C44 UNK5SH16.1
HDVI_990_13-CH54S: SLOT13.D41 UNK5K13.5 UNK5TP_NPG/ATB1_S.1
HDVI_991_13-CH55BP: SLOT13.B41
HDVI_991_13-CH55F: SLOT13.F38 UNK5K14.4 UNK5TP_NCHG/ATB0_F.1
HDVI_991_13-CH55GS: SLOT13.E44 UNK5SH14.1
HDVI_991_13-CH55S: SLOT13.B39 UNK5K14.5
HDVI_992_13-CH56BP: SLOT13.C39
HDVI_992_13-CH56F: SITE5.F19(LSOUT2 / SUSPEND_F) SLOT13.E39 UNK5CS19.1 UNK5K8.6 UNK5SH38.2 UNK5TP_LSOUT2/SUSPEND_F.1
HDVI_992_13-CH56GS: SLOT13.C43 UNK5SH30.2
HDVI_992_13-CH56S: SITE5.S19(LSOUT2 / SUSPEND_S) SLOT13.D39 UNK5TP_LSOUT2/SUSPEND1_S.1
HDVI_993_13-CH57BP: SLOT13.A41
HDVI_993_13-CH57F: SLOT13.C40 SLOT13.E40 UNK7K10.2
HDVI_993_13-CH57GS: SLOT13.A43 SLOT13.B43 UNK7SH9.1
HDVI_993_13-CH57S: SLOT13.A39 SLOT13.A40 UNK7K10.7
HDVI_994_13-CH58BP: SLOT13.B42
HDVI_995_13-CH59BP: SLOT13.C36
HDVI_995_13-CH59F: SITE7.F25(VSYS_F) SLOT13.G32 SLOT13.G36 UNK7CS25.1 UNK7K2.3 UNK7TP_VSYS_F.1
HDVI_995_13-CH59GS: SLOT13.B38 SLOT13.D38 UNK7SH7.2
HDVI_995_13-CH59S: SITE7.S25(VSYS_S) SLOT13.E32 SLOT13.E36 UNK7TP_VSYS_S.1
HDVI_996_13-CH60BP: SLOT13.D34
HDVI_997_13-CH61BP: SLOT13.E24
HDVI_997_13-CH61F: SITE7.F5(LSOUT1 / ILIM1_F) SLOT13.E28 UNK7CS5.2 UNK7K8.3 UNK7SH36.2 UNK7TP_LSOUT1_F.1
HDVI_997_13-CH61GS: SLOT13.A36 UNK7SH32.1
HDVI_997_13-CH61S: SITE7.S5(LSOUT1 / ILIM1_S) SLOT13.F26 UNK7TP_LSOUT1_S.1
HDVI_998_13-CH62BP: SLOT13.F18
HDVI_998_13-CH62F: SLOT13.G20 UNK7K13.4 UNK7TP_NPG/ATB1_F.1
HDVI_998_13-CH62GS: SLOT13.B10 UNK7SH16.1
HDVI_998_13-CH62S: SLOT13.E16 UNK7K13.5 UNK7TP_NPG/ATB1_S.1
HDVI_999_13-CH63BP: SLOT13.E12
HDVI_999_13-CH63F: SLOT13.F14 UNK7K14.4 UNK7TP_NCHG/ATB0_F.1
HDVI_999_13-CH63GS: SLOT13.A8 UNK7SH14.1
HDVI_999_13-CH63S: SLOT13.D10 UNK7K14.5
HDVI_1000_13-CH64BP: SLOT13.E8
HDVI_1000_13-CH64F: SITE7.F19(LSOUT2 / SUSPEND_F) SLOT13.G8 UNK7CS19.1 UNK7K8.6 UNK7SH38.2 UNK7TP_LSOUT2/SUSPEND_F.1
HDVI_1000_13-CH64GS: SLOT13.C8 UNK7SH30.2
HDVI_1000_13-CH64S: SITE7.S19(LSOUT2 / SUSPEND_S) SLOT13.F6 UNK7TP_LSOUT2/SUSPEND1_S.1
HDVI_1001_13-CH65BP: SLOT13.B34
HDVI_1001_13-CH65F: SLOT13.F30 SLOT13.F34 UNK13K10.2
HDVI_1001_13-CH65GS: SLOT13.A32 SLOT13.B30 UNK13SH9.1
HDVI_1001_13-CH65S: SLOT13.C28 SLOT13.C32 UNK13K10.7
HDVI_1002_13-CH66BP: SLOT13.D30
HDVI_1003_13-CH67BP: SLOT13.B26
HDVI_1003_13-CH67F: SITE13.F25(VSYS_F) SLOT13.G24 SLOT13.G28 UNK13CS25.1 UNK13K2.3 UNK13TP_VSYS_F.1
HDVI_1003_13-CH67GS: SLOT13.A24 SLOT13.A28 UNK13SH7.2
HDVI_1003_13-CH67S: SITE13.S25(VSYS_S) SLOT13.B22 SLOT13.D26 UNK13TP_VSYS_S.1
HDVI_1004_13-CH68BP: SLOT13.C24
HDVI_1005_13-CH69BP: SLOT13.C20
HDVI_1005_13-CH69F: SITE13.F5(LSOUT1 / ILIM1_F) SLOT13.F22 UNK13CS5.2 UNK13K8.3 UNK13SH36.2 UNK13TP_LSOUT1_F.1
HDVI_1005_13-CH69GS: SLOT13.A20 UNK13SH32.1
HDVI_1005_13-CH69S: SITE13.S5(LSOUT1 / ILIM1_S) SLOT13.D22 UNK13TP_LSOUT1_S.1
HDVI_1006_13-CH70BP: SLOT13.D18
HDVI_1006_13-CH70F: SLOT13.G16 UNK13K13.4 UNK13TP_NPG/ATB1_F.1
HDVI_1006_13-CH70GS: SLOT13.B18 UNK13SH16.1
HDVI_1006_13-CH70S: SLOT13.E20 UNK13K13.5 UNK13TP_NPG/ATB1_S.1
HDVI_1007_13-CH71BP: SLOT13.C16
HDVI_1007_13-CH71F: SLOT13.G12 UNK13K14.4 UNK13TP_NCHG/ATB0_F.1
HDVI_1007_13-CH71GS: SLOT13.A16 UNK13SH14.1
HDVI_1007_13-CH71S: SLOT13.B14 UNK13K14.5
HDVI_1008_13-CH72BP: SLOT13.C12
HDVI_1008_13-CH72F: SITE13.F19(LSOUT2 / SUSPEND_F) SLOT13.F10 UNK13CS19.1 UNK13K8.6 UNK13SH38.2 UNK13TP_LSOUT2/SUSPEND_F.1
HDVI_1008_13-CH72GS: SLOT13.A12 UNK13SH30.2
HDVI_1008_13-CH72S: SITE13.S19(LSOUT2 / SUSPEND_S) SLOT13.D14 UNK13TP_LSOUT2/SUSPEND1_S.1
HV_AUTHZD_N: SLOT0.B37
LB_PRESENT_N: SLOT0.D41 UNK0BS2.1
LB_REG_ADDR0: SLOT0.A18
LB_REG_ADDR1: SLOT0.B18
LB_REG_ADDR2: SLOT0.C18
LB_REG_ADDR3: SLOT0.D18
LB_REG_ADDR4: SLOT0.D20
LB_REG_ADDR5: SLOT0.E20
LB_REG_ADDR6: SLOT0.F20
LB_REG_ADDR7: SLOT0.G20
LB_REG_DATA0: SLOT0.B20
LB_REG_DATA1: SLOT0.C20
LB_REG_DATA2: SLOT0.A22
LB_REG_DATA3: SLOT0.B22
LB_REG_DATA4: SLOT0.C22
LB_REG_DATA5: SLOT0.D22
LB_REG_DATA6: SLOT0.E22
LB_REG_DATA7: SLOT0.F22
LB_REG_RD_N: SLOT0.D16
LB_REG_WR_N: SLOT0.C16
REG1_P3V3: C84.1 C85.1 C86.1 C87.1 C88.1 C89.1 C90.1 C103.1 R7.1 R8.1 R9.1 R10.1 REG1_P3V3.1(TP) U4.12(VDD) U44.5(VOUT)
REG1_P_5V: C101.1 R383.1 REG1_P_5V.1(TP) U47.2(OUT) U47.4(TAB)
RFNH1_CPE_CPLD_CLK: SLOT0.A51
RFNH1_CPE_CPLD_CS: SLOT0.A59
RFNH1_CPE_CPLD_DAT_IN: SLOT0.A55
RFNH1_CPE_CPLD_DAT_OUT: SLOT0.A49
RFNH2_CPE_CPLD_CLK: SLOT0.F53
RFNH2_CPE_CPLD_CS: SLOT0.F61
RFNH2_CPE_CPLD_DAT_IN: SLOT0.F57
RFNH2_CPE_CPLD_DAT_OUT: SLOT0.F49
RLY_5V: BC5.1 BC6.1 RLY_5V1.1(A) SLOT0.A6 SLOT0.B6 SLOT0.C6 SLOT0.D6 SLOT0.E6 T_RLY_5V.1(TP)
S1_AVSS_GS: UNK1R13.2 UNK1R14.2 UNK1RS1.1 UNK1RS2.1 UNK1RS5.1
S1_AVSS_S[01]: SITE1.S3(AVSS_S[01]) UNK1RS1.2 UNK1RS3.2
S1_EPAD2: SITE1.EPAD2(AVSS[02]) SITE1.G6 UNK1RS5.2
S1_NCHG / ATB0_F: SITE1.F26(NCHG / ATB0_F) UNK1CS26.2 UNK1K14.3
S1_NCHG / ATB0_S: SITE1.S26(NCHG / ATB0_S) UNK1K14.6 UNK1TP_NCHG/ATB0_S.1
S1_NPG / ATB1_F: SITE1.F27(NPG / ATB1_F) UNK1CS27.2 UNK1K13.3
S1_NPG / ATB1_S: SITE1.S27(NPG / ATB1_S) UNK1K13.6
S1_NTC: SITE1.F7(NTC_F) SITE1.S7(NTC_S) UNK1K4.3 UNK1TP_NTC.1
S1_NTC_K4K: UNK1K4.2 UNK1K5.3 UNK1K6.3 UNK1K7.3
S1_SCL: SITE1.F15(SCL_F) SITE1.S15(SCL_S) UNK1K9.6 UNK1SH40.2 UNK1TP_SCL.1
S1_SCL_K9R: UNK1K9.5 UNK1R7.2
S1_SDA: SITE1.F14(SDA_F) SITE1.S14(SDA_S) UNK1K9.3 UNK1SH41.2 UNK1TP_SDA.1
S1_SDA_K9R: UNK1K9.4 UNK1R8.2
S1_VBAT_F: SITE1.F1(VBAT_F) UNK1CS1.1 UNK1K10.3 UNK1K11.3 UNK1K12.3 UNK1TP_VBAT_F.1
S1_VBAT_K11C: UNK1C6.1 UNK1K11.4
S1_VBAT_K12: UNK1C9.1 UNK1K12.4 UNK1TP_REF_5V.1 UNK1U1.6
S1_VBAT_S: SITE1.S1(VBAT_S) UNK1K10.6 UNK1K12.6 UNK1TP_VBAT_S.1
S1_VBUS_CK: UNK1C2.2 UNK1K1.3
S1_VSET: SITE1.F8(VSET_F) SITE1.S8(VSET_S) UNK1K3.3 UNK1TP_VEST.1
S1_VSET_K3R: UNK1K3.2 UNK1R1.2
S2_AVSS_GS: UNK2R13.2 UNK2R14.2 UNK2RS1.1 UNK2RS2.1 UNK2RS5.1
S2_AVSS_S[01]: SITE2.S3(AVSS_S[01]) UNK2RS1.2 UNK2RS3.2
S2_EPAD2: SITE2.EPAD2(AVSS[02]) SITE2.G6 UNK2RS5.2
S2_NCHG / ATB0_F: SITE2.F26(NCHG / ATB0_F) UNK2CS26.2 UNK2K14.3
S2_NCHG / ATB0_S: SITE2.S26(NCHG / ATB0_S) UNK2K14.6 UNK2TP_NCHG/ATB0_S.1
S2_NPG / ATB1_F: SITE2.F27(NPG / ATB1_F) UNK2CS27.2 UNK2K13.3
S2_NPG / ATB1_S: SITE2.S27(NPG / ATB1_S) UNK2K13.6
S2_NTC: SITE2.F7(NTC_F) SITE2.S7(NTC_S) UNK2K4.3 UNK2TP_NTC.1
S2_NTC_K4K: UNK2K4.2 UNK2K5.3 UNK2K6.3 UNK2K7.3
S2_SCL: SITE2.F15(SCL_F) SITE2.S15(SCL_S) UNK2K9.6 UNK2SH40.2 UNK2TP_SCL.1
S2_SCL_K9R: UNK2K9.5 UNK2R7.2
S2_SDA: SITE2.F14(SDA_F) SITE2.S14(SDA_S) UNK2K9.3 UNK2SH41.2 UNK2TP_SDA.1
S2_SDA_K9R: UNK2K9.4 UNK2R8.2
S2_VBAT_F: SITE2.F1(VBAT_F) UNK2CS1.1 UNK2K10.3 UNK2K11.3 UNK2K12.3 UNK2TP_VBAT_F.1
S2_VBAT_K11C: UNK2C6.1 UNK2K11.4
S2_VBAT_K12: UNK2C9.1 UNK2K12.4 UNK2TP_REF_5V.1 UNK2U1.6
S2_VBAT_S: SITE2.S1(VBAT_S) UNK2K10.6 UNK2K12.6 UNK2TP_VBAT_S.1
S2_VBUS_CK: UNK2C2.2 UNK2K1.3
S2_VSET: SITE2.F8(VSET_F) SITE2.S8(VSET_S) UNK2K3.3 UNK2TP_VEST.1
S2_VSET_K3R: UNK2K3.2 UNK2R1.2
S3_AVSS_GS: UNK3R13.2 UNK3R14.2 UNK3RS1.1 UNK3RS2.1 UNK3RS5.1
S3_AVSS_S[01]: SITE3.S3(AVSS_S[01]) UNK3RS1.2 UNK3RS3.2
S3_EPAD2: SITE3.EPAD2(AVSS[02]) SITE3.G6 UNK3RS5.2
S3_NCHG / ATB0_F: SITE3.F26(NCHG / ATB0_F) UNK3CS26.2 UNK3K14.3
S3_NCHG / ATB0_S: SITE3.S26(NCHG / ATB0_S) UNK3K14.6 UNK3TP_NCHG/ATB0_S.1
S3_NPG / ATB1_F: SITE3.F27(NPG / ATB1_F) UNK3CS27.2 UNK3K13.3
S3_NPG / ATB1_S: SITE3.S27(NPG / ATB1_S) UNK3K13.6
S3_NTC: SITE3.F7(NTC_F) SITE3.S7(NTC_S) UNK3K4.3 UNK3TP_NTC.1
S3_NTC_K4K: UNK3K4.2 UNK3K5.3 UNK3K6.3 UNK3K7.3
S3_SCL: SITE3.F15(SCL_F) SITE3.S15(SCL_S) UNK3K9.6 UNK3SH40.2 UNK3TP_SCL.1
S3_SCL_K9R: UNK3K9.5 UNK3R7.2
S3_SDA: SITE3.F14(SDA_F) SITE3.S14(SDA_S) UNK3K9.3 UNK3SH41.2 UNK3TP_SDA.1
S3_SDA_K9R: UNK3K9.4 UNK3R8.2
S3_VBAT_F: SITE3.F1(VBAT_F) UNK3CS1.1 UNK3K10.3 UNK3K11.3 UNK3K12.3 UNK3TP_VBAT_F.1
S3_VBAT_K11C: UNK3C6.1 UNK3K11.4
S3_VBAT_K12: UNK3C9.1 UNK3K12.4 UNK3TP_REF_5V.1 UNK3U1.6
S3_VBAT_S: SITE3.S1(VBAT_S) UNK3K10.6 UNK3K12.6 UNK3TP_VBAT_S.1
S3_VBUS_CK: UNK3C2.2 UNK3K1.3
S3_VSET: SITE3.F8(VSET_F) SITE3.S8(VSET_S) UNK3K3.3 UNK3TP_VEST.1
S3_VSET_K3R: UNK3K3.2 UNK3R1.2
S4_AVSS_GS: UNK4R13.2 UNK4R14.2 UNK4RS1.1 UNK4RS2.1 UNK4RS5.1
S4_AVSS_S[01]: SITE4.S3(AVSS_S[01]) UNK4RS1.2 UNK4RS3.2
S4_EPAD2: SITE4.EPAD2(AVSS[02]) SITE4.G6 UNK4RS5.2
S4_NCHG / ATB0_F: SITE4.F26(NCHG / ATB0_F) UNK4CS26.2 UNK4K14.3
S4_NCHG / ATB0_S: SITE4.S26(NCHG / ATB0_S) UNK4K14.6 UNK4TP_NCHG/ATB0_S.1
S4_NPG / ATB1_F: SITE4.F27(NPG / ATB1_F) UNK4CS27.2 UNK4K13.3
S4_NPG / ATB1_S: SITE4.S27(NPG / ATB1_S) UNK4K13.6
S4_NTC: SITE4.F7(NTC_F) SITE4.S7(NTC_S) UNK4K4.3 UNK4TP_NTC.1
S4_NTC_K4K: UNK4K4.2 UNK4K5.3 UNK4K6.3 UNK4K7.3
S4_SCL: SITE4.F15(SCL_F) SITE4.S15(SCL_S) UNK4K9.6 UNK4SH40.2 UNK4TP_SCL.1
S4_SCL_K9R: UNK4K9.5 UNK4R7.2
S4_SDA: SITE4.F14(SDA_F) SITE4.S14(SDA_S) UNK4K9.3 UNK4SH41.2 UNK4TP_SDA.1
S4_SDA_K9R: UNK4K9.4 UNK4R8.2
S4_VBAT_F: SITE4.F1(VBAT_F) UNK4CS1.1 UNK4K10.3 UNK4K11.3 UNK4K12.3 UNK4TP_VBAT_F.1
S4_VBAT_K11C: UNK4C6.1 UNK4K11.4
S4_VBAT_K12: UNK4C9.1 UNK4K12.4 UNK4TP_REF_5V.1 UNK4U1.6
S4_VBAT_S: SITE4.S1(VBAT_S) UNK4K10.6 UNK4K12.6 UNK4TP_VBAT_S.1
S4_VBUS_CK: UNK4C2.2 UNK4K1.3
S4_VSET: SITE4.F8(VSET_F) SITE4.S8(VSET_S) UNK4K3.3 UNK4TP_VEST.1
S4_VSET_K3R: UNK4K3.2 UNK4R1.2
S5_AVSS_GS: UNK5R13.2 UNK5R14.2 UNK5RS1.1 UNK5RS2.1 UNK5RS5.1
S5_AVSS_S[01]: SITE5.S3(AVSS_S[01]) UNK5RS1.2 UNK5RS3.2
S5_EPAD2: SITE5.EPAD2(AVSS[02]) SITE5.G6 UNK5RS5.2
S5_NCHG / ATB0_F: SITE5.F26(NCHG / ATB0_F) UNK5CS26.2 UNK5K14.3
S5_NCHG / ATB0_S: SITE5.S26(NCHG / ATB0_S) UNK5K14.6 UNK5TP_NCHG/ATB0_S.1
S5_NPG / ATB1_F: SITE5.F27(NPG / ATB1_F) UNK5CS27.2 UNK5K13.3
S5_NPG / ATB1_S: SITE5.S27(NPG / ATB1_S) UNK5K13.6
S5_NTC: SITE5.F7(NTC_F) SITE5.S7(NTC_S) UNK5K4.3 UNK5TP_NTC.1
S5_NTC_K4K: UNK5K4.2 UNK5K5.3 UNK5K6.3 UNK5K7.3
S5_SCL: SITE5.F15(SCL_F) SITE5.S15(SCL_S) UNK5K9.6 UNK5SH40.2 UNK5TP_SCL.1
S5_SCL_K9R: UNK5K9.5 UNK5R7.2
S5_SDA: SITE5.F14(SDA_F) SITE5.S14(SDA_S) UNK5K9.3 UNK5SH41.2 UNK5TP_SDA.1
S5_SDA_K9R: UNK5K9.4 UNK5R8.2
S5_VBAT_F: SITE5.F1(VBAT_F) UNK5CS1.1 UNK5K10.3 UNK5K11.3 UNK5K12.3 UNK5TP_VBAT_F.1
S5_VBAT_K11C: UNK5C6.1 UNK5K11.4
S5_VBAT_K12: UNK5C9.1 UNK5K12.4 UNK5TP_REF_5V.1 UNK5U1.6
S5_VBAT_S: SITE5.S1(VBAT_S) UNK5K10.6 UNK5K12.6 UNK5TP_VBAT_S.1
S5_VBUS_CK: UNK5C2.2 UNK5K1.3
S5_VSET: SITE5.F8(VSET_F) SITE5.S8(VSET_S) UNK5K3.3 UNK5TP_VEST.1
S5_VSET_K3R: UNK5K3.2 UNK5R1.2
S6_AVSS_GS: UNK6R13.2 UNK6R14.2 UNK6RS1.1 UNK6RS2.1 UNK6RS5.1
S6_AVSS_S[01]: SITE6.S3(AVSS_S[01]) UNK6RS1.2 UNK6RS3.2
S6_EPAD2: SITE6.EPAD2(AVSS[02]) SITE6.G6 UNK6RS5.2
S6_NCHG / ATB0_F: SITE6.F26(NCHG / ATB0_F) UNK6CS26.2 UNK6K14.3
S6_NCHG / ATB0_S: SITE6.S26(NCHG / ATB0_S) UNK6K14.6 UNK6TP_NCHG/ATB0_S.1
S6_NPG / ATB1_F: SITE6.F27(NPG / ATB1_F) UNK6CS27.2 UNK6K13.3
S6_NPG / ATB1_S: SITE6.S27(NPG / ATB1_S) UNK6K13.6
S6_NTC: SITE6.F7(NTC_F) SITE6.S7(NTC_S) UNK6K4.3 UNK6TP_NTC.1
S6_NTC_K4K: UNK6K4.2 UNK6K5.3 UNK6K6.3 UNK6K7.3
S6_SCL: SITE6.F15(SCL_F) SITE6.S15(SCL_S) UNK6K9.6 UNK6SH40.2 UNK6TP_SCL.1
S6_SCL_K9R: UNK6K9.5 UNK6R7.2
S6_SDA: SITE6.F14(SDA_F) SITE6.S14(SDA_S) UNK6K9.3 UNK6SH41.2 UNK6TP_SDA.1
S6_SDA_K9R: UNK6K9.4 UNK6R8.2
S6_VBAT_F: SITE6.F1(VBAT_F) UNK6CS1.1 UNK6K10.3 UNK6K11.3 UNK6K12.3 UNK6TP_VBAT_F.1
S6_VBAT_K11C: UNK6C6.1 UNK6K11.4
S6_VBAT_K12: UNK6C9.1 UNK6K12.4 UNK6TP_REF_5V.1 UNK6U1.6
S6_VBAT_S: SITE6.S1(VBAT_S) UNK6K10.6 UNK6K12.6 UNK6TP_VBAT_S.1
S6_VBUS_CK: UNK6C2.2 UNK6K1.3
S6_VSET: SITE6.F8(VSET_F) SITE6.S8(VSET_S) UNK6K3.3 UNK6TP_VEST.1
S6_VSET_K3R: UNK6K3.2 UNK6R1.2
S7_AVSS_GS: UNK7R13.2 UNK7R14.2 UNK7RS1.1 UNK7RS2.1 UNK7RS5.1
S7_AVSS_S[01]: SITE7.S3(AVSS_S[01]) UNK7RS1.2 UNK7RS3.2
S7_EPAD2: SITE7.EPAD2(AVSS[02]) SITE7.G6 UNK7RS5.2
S7_NCHG / ATB0_F: SITE7.F26(NCHG / ATB0_F) UNK7CS26.2 UNK7K14.3
S7_NCHG / ATB0_S: SITE7.S26(NCHG / ATB0_S) UNK7K14.6 UNK7TP_NCHG/ATB0_S.1
S7_NPG / ATB1_F: SITE7.F27(NPG / ATB1_F) UNK7CS27.2 UNK7K13.3
S7_NPG / ATB1_S: SITE7.S27(NPG / ATB1_S) UNK7K13.6
S7_NTC: SITE7.F7(NTC_F) SITE7.S7(NTC_S) UNK7K4.3 UNK7TP_NTC.1
S7_NTC_K4K: UNK7K4.2 UNK7K5.3 UNK7K6.3 UNK7K7.3
S7_SCL: SITE7.F15(SCL_F) SITE7.S15(SCL_S) UNK7K9.6 UNK7SH40.2 UNK7TP_SCL.1
S7_SCL_K9R: UNK7K9.5 UNK7R7.2
S7_SDA: SITE7.F14(SDA_F) SITE7.S14(SDA_S) UNK7K9.3 UNK7SH41.2 UNK7TP_SDA.1
S7_SDA_K9R: UNK7K9.4 UNK7R8.2
S7_VBAT_F: SITE7.F1(VBAT_F) UNK7CS1.1 UNK7K10.3 UNK7K11.3 UNK7K12.3 UNK7TP_VBAT_F.1
S7_VBAT_K11C: UNK7C6.1 UNK7K11.4
S7_VBAT_K12: UNK7C9.1 UNK7K12.4 UNK7TP_REF_5V.1 UNK7U1.6
S7_VBAT_S: SITE7.S1(VBAT_S) UNK7K10.6 UNK7K12.6 UNK7TP_VBAT_S.1
S7_VBUS_CK: UNK7C2.2 UNK7K1.3
S7_VSET: SITE7.F8(VSET_F) SITE7.S8(VSET_S) UNK7K3.3 UNK7TP_VEST.1
S7_VSET_K3R: UNK7K3.2 UNK7R1.2
S8_AVSS_GS: UNK8R13.2 UNK8R14.2 UNK8RS1.1 UNK8RS2.1 UNK8RS5.1
S8_AVSS_S[01]: SITE8.S3(AVSS_S[01]) UNK8RS1.2 UNK8RS3.2
S8_EPAD2: SITE8.EPAD2(AVSS[02]) SITE8.G6 UNK8RS5.2
S8_NCHG / ATB0_F: SITE8.F26(NCHG / ATB0_F) UNK8CS26.2 UNK8K14.3
S8_NCHG / ATB0_S: SITE8.S26(NCHG / ATB0_S) UNK8K14.6 UNK8TP_NCHG/ATB0_S.1
S8_NPG / ATB1_F: SITE8.F27(NPG / ATB1_F) UNK8CS27.2 UNK8K13.3
S8_NPG / ATB1_S: SITE8.S27(NPG / ATB1_S) UNK8K13.6
S8_NTC: SITE8.F7(NTC_F) SITE8.S7(NTC_S) UNK8K4.3 UNK8TP_NTC.1
S8_NTC_K4K: UNK8K4.2 UNK8K5.3 UNK8K6.3 UNK8K7.3
S8_SCL: SITE8.F15(SCL_F) SITE8.S15(SCL_S) UNK8K9.6 UNK8SH40.2 UNK8TP_SCL.1
S8_SCL_K9R: UNK8K9.5 UNK8R7.2
S8_SDA: SITE8.F14(SDA_F) SITE8.S14(SDA_S) UNK8K9.3 UNK8SH41.2 UNK8TP_SDA.1
S8_SDA_K9R: UNK8K9.4 UNK8R8.2
S8_VBAT_F: SITE8.F1(VBAT_F) UNK8CS1.1 UNK8K10.3 UNK8K11.3 UNK8K12.3 UNK8TP_VBAT_F.1
S8_VBAT_K11C: UNK8C6.1 UNK8K11.4
S8_VBAT_K12: UNK8C9.1 UNK8K12.4 UNK8TP_REF_5V.1 UNK8U1.6
S8_VBAT_S: SITE8.S1(VBAT_S) UNK8K10.6 UNK8K12.6 UNK8TP_VBAT_S.1
S8_VBUS_CK: UNK8C2.2 UNK8K1.3
S8_VSET: SITE8.F8(VSET_F) SITE8.S8(VSET_S) UNK8K3.3 UNK8TP_VEST.1
S8_VSET_K3R: UNK8K3.2 UNK8R1.2
S9_AVSS_GS: UNK9R13.2 UNK9R14.2 UNK9RS1.1 UNK9RS2.1 UNK9RS5.1
S9_AVSS_S[01]: SITE9.S3(AVSS_S[01]) UNK9RS1.2 UNK9RS3.2
S9_EPAD2: SITE9.EPAD2(AVSS[02]) SITE9.G6 UNK9RS5.2
S9_NCHG / ATB0_F: SITE9.F26(NCHG / ATB0_F) UNK9CS26.2 UNK9K14.3
S9_NCHG / ATB0_S: SITE9.S26(NCHG / ATB0_S) UNK9K14.6 UNK9TP_NCHG/ATB0_S.1
S9_NPG / ATB1_F: SITE9.F27(NPG / ATB1_F) UNK9CS27.2 UNK9K13.3
S9_NPG / ATB1_S: SITE9.S27(NPG / ATB1_S) UNK9K13.6
S9_NTC: SITE9.F7(NTC_F) SITE9.S7(NTC_S) UNK9K4.3 UNK9TP_NTC.1
S9_NTC_K4K: UNK9K4.2 UNK9K5.3 UNK9K6.3 UNK9K7.3
S9_SCL: SITE9.F15(SCL_F) SITE9.S15(SCL_S) UNK9K9.6 UNK9SH40.2 UNK9TP_SCL.1
S9_SCL_K9R: UNK9K9.5 UNK9R7.2
S9_SDA: SITE9.F14(SDA_F) SITE9.S14(SDA_S) UNK9K9.3 UNK9SH41.2 UNK9TP_SDA.1
S9_SDA_K9R: UNK9K9.4 UNK9R8.2
S9_VBAT_F: SITE9.F1(VBAT_F) UNK9CS1.1 UNK9K10.3 UNK9K11.3 UNK9K12.3 UNK9TP_VBAT_F.1
S9_VBAT_K11C: UNK9C6.1 UNK9K11.4
S9_VBAT_K12: UNK9C9.1 UNK9K12.4 UNK9TP_REF_5V.1 UNK9U1.6
S9_VBAT_S: SITE9.S1(VBAT_S) UNK9K10.6 UNK9K12.6 UNK9TP_VBAT_S.1
S9_VBUS_CK: UNK9C2.2 UNK9K1.3
S9_VSET: SITE9.F8(VSET_F) SITE9.S8(VSET_S) UNK9K3.3 UNK9TP_VEST.1
S9_VSET_K3R: UNK9K3.2 UNK9R1.2
S10_AVSS_GS: UNK10R13.2 UNK10R14.2 UNK10RS1.1 UNK10RS2.1 UNK10RS5.1
S10_AVSS_S[01]: SITE10.S3(AVSS_S[01]) UNK10RS1.2 UNK10RS3.2
S10_EPAD2: SITE10.EPAD2(AVSS[02]) SITE10.G6 UNK10RS5.2
S10_NCHG / ATB0_F: SITE10.F26(NCHG / ATB0_F) UNK10CS26.2 UNK10K14.3
S10_NCHG / ATB0_S: SITE10.S26(NCHG / ATB0_S) UNK10K14.6 UNK10TP_NCHG/ATB0_S.1
S10_NPG / ATB1_F: SITE10.F27(NPG / ATB1_F) UNK10CS27.2 UNK10K13.3
S10_NPG / ATB1_S: SITE10.S27(NPG / ATB1_S) UNK10K13.6
S10_NTC: SITE10.F7(NTC_F) SITE10.S7(NTC_S) UNK10K4.3 UNK10TP_NTC.1
S10_NTC_K4K: UNK10K4.2 UNK10K5.3 UNK10K6.3 UNK10K7.3
S10_SCL: SITE10.F15(SCL_F) SITE10.S15(SCL_S) UNK10K9.6 UNK10SH40.2 UNK10TP_SCL.1
S10_SCL_K9R: UNK10K9.5 UNK10R7.2
S10_SDA: SITE10.F14(SDA_F) SITE10.S14(SDA_S) UNK10K9.3 UNK10SH41.2 UNK10TP_SDA.1
S10_SDA_K9R: UNK10K9.4 UNK10R8.2
S10_VBAT_F: SITE10.F1(VBAT_F) UNK10CS1.1 UNK10K10.3 UNK10K11.3 UNK10K12.3 UNK10TP_VBAT_F.1
S10_VBAT_K11C: UNK10C6.1 UNK10K11.4
S10_VBAT_K12: UNK10C9.1 UNK10K12.4 UNK10TP_REF_5V.1 UNK10U1.6
S10_VBAT_S: SITE10.S1(VBAT_S) UNK10K10.6 UNK10K12.6 UNK10TP_VBAT_S.1
S10_VBUS_CK: UNK10C2.2 UNK10K1.3
S10_VSET: SITE10.F8(VSET_F) SITE10.S8(VSET_S) UNK10K3.3 UNK10TP_VEST.1
S10_VSET_K3R: UNK10K3.2 UNK10R1.2
S11_AVSS_GS: UNK11R13.2 UNK11R14.2 UNK11RS1.1 UNK11RS2.1 UNK11RS5.1
S11_AVSS_S[01]: SITE11.S3(AVSS_S[01]) UNK11RS1.2 UNK11RS3.2
S11_EPAD2: SITE11.EPAD2(AVSS[02]) SITE11.G6 UNK11RS5.2
S11_NCHG / ATB0_F: SITE11.F26(NCHG / ATB0_F) UNK11CS26.2 UNK11K14.3
S11_NCHG / ATB0_S: SITE11.S26(NCHG / ATB0_S) UNK11K14.6 UNK11TP_NCHG/ATB0_S.1
S11_NPG / ATB1_F: SITE11.F27(NPG / ATB1_F) UNK11CS27.2 UNK11K13.3
S11_NPG / ATB1_S: SITE11.S27(NPG / ATB1_S) UNK11K13.6
S11_NTC: SITE11.F7(NTC_F) SITE11.S7(NTC_S) UNK11K4.3 UNK11TP_NTC.1
S11_NTC_K4K: UNK11K4.2 UNK11K5.3 UNK11K6.3 UNK11K7.3
S11_SCL: SITE11.F15(SCL_F) SITE11.S15(SCL_S) UNK11K9.6 UNK11SH40.2 UNK11TP_SCL.1
S11_SCL_K9R: UNK11K9.5 UNK11R7.2
S11_SDA: SITE11.F14(SDA_F) SITE11.S14(SDA_S) UNK11K9.3 UNK11SH41.2 UNK11TP_SDA.1
S11_SDA_K9R: UNK11K9.4 UNK11R8.2
S11_VBAT_F: SITE11.F1(VBAT_F) UNK11CS1.1 UNK11K10.3 UNK11K11.3 UNK11K12.3 UNK11TP_VBAT_F.1
S11_VBAT_K11C: UNK11C6.1 UNK11K11.4
S11_VBAT_K12: UNK11C9.1 UNK11K12.4 UNK11TP_REF_5V.1 UNK11U1.6
S11_VBAT_S: SITE11.S1(VBAT_S) UNK11K10.6 UNK11K12.6 UNK11TP_VBAT_S.1
S11_VBUS_CK: UNK11C2.2 UNK11K1.3
S11_VSET: SITE11.F8(VSET_F) SITE11.S8(VSET_S) UNK11K3.3 UNK11TP_VEST.1
S11_VSET_K3R: UNK11K3.2 UNK11R1.2
S12_AVSS_GS: UNK12R13.2 UNK12R14.2 UNK12RS1.1 UNK12RS2.1 UNK12RS5.1
S12_AVSS_S[01]: SITE12.S3(AVSS_S[01]) UNK12RS1.2 UNK12RS3.2
S12_EPAD2: SITE12.EPAD2(AVSS[02]) SITE12.G6 UNK12RS5.2
S12_NCHG / ATB0_F: SITE12.F26(NCHG / ATB0_F) UNK12CS26.2 UNK12K14.3
S12_NCHG / ATB0_S: SITE12.S26(NCHG / ATB0_S) UNK12K14.6 UNK12TP_NCHG/ATB0_S.1
S12_NPG / ATB1_F: SITE12.F27(NPG / ATB1_F) UNK12CS27.2 UNK12K13.3
S12_NPG / ATB1_S: SITE12.S27(NPG / ATB1_S) UNK12K13.6
S12_NTC: SITE12.F7(NTC_F) SITE12.S7(NTC_S) UNK12K4.3 UNK12TP_NTC.1
S12_NTC_K4K: UNK12K4.2 UNK12K5.3 UNK12K6.3 UNK12K7.3
S12_SCL: SITE12.F15(SCL_F) SITE12.S15(SCL_S) UNK12K9.6 UNK12SH40.2 UNK12TP_SCL.1
S12_SCL_K9R: UNK12K9.5 UNK12R7.2
S12_SDA: SITE12.F14(SDA_F) SITE12.S14(SDA_S) UNK12K9.3 UNK12SH41.2 UNK12TP_SDA.1
S12_SDA_K9R: UNK12K9.4 UNK12R8.2
S12_VBAT_F: SITE12.F1(VBAT_F) UNK12CS1.1 UNK12K10.3 UNK12K11.3 UNK12K12.3 UNK12TP_VBAT_F.1
S12_VBAT_K11C: UNK12C6.1 UNK12K11.4
S12_VBAT_K12: UNK12C9.1 UNK12K12.4 UNK12TP_REF_5V.1 UNK12U1.6
S12_VBAT_S: SITE12.S1(VBAT_S) UNK12K10.6 UNK12K12.6 UNK12TP_VBAT_S.1
S12_VBUS_CK: UNK12C2.2 UNK12K1.3
S12_VSET: SITE12.F8(VSET_F) SITE12.S8(VSET_S) UNK12K3.3 UNK12TP_VEST.1
S12_VSET_K3R: UNK12K3.2 UNK12R1.2
S13_AVSS_GS: UNK13R13.2 UNK13R14.2 UNK13RS1.1 UNK13RS2.1 UNK13RS5.1
S13_AVSS_S[01]: SITE13.S3(AVSS_S[01]) UNK13RS1.2 UNK13RS3.2
S13_EPAD2: SITE13.EPAD2(AVSS[02]) SITE13.G6 UNK13RS5.2
S13_NCHG / ATB0_F: SITE13.F26(NCHG / ATB0_F) UNK13CS26.2 UNK13K14.3
S13_NCHG / ATB0_S: SITE13.S26(NCHG / ATB0_S) UNK13K14.6 UNK13TP_NCHG/ATB0_S.1
S13_NPG / ATB1_F: SITE13.F27(NPG / ATB1_F) UNK13CS27.2 UNK13K13.3
S13_NPG / ATB1_S: SITE13.S27(NPG / ATB1_S) UNK13K13.6
S13_NTC: SITE13.F7(NTC_F) SITE13.S7(NTC_S) UNK13K4.3 UNK13TP_NTC.1
S13_NTC_K4K: UNK13K4.2 UNK13K5.3 UNK13K6.3 UNK13K7.3
S13_SCL: SITE13.F15(SCL_F) SITE13.S15(SCL_S) UNK13K9.6 UNK13SH40.2 UNK13TP_SCL.1
S13_SCL_K9R: UNK13K9.5 UNK13R7.2
S13_SDA: SITE13.F14(SDA_F) SITE13.S14(SDA_S) UNK13K9.3 UNK13SH41.2 UNK13TP_SDA.1
S13_SDA_K9R: UNK13K9.4 UNK13R8.2
S13_VBAT_F: SITE13.F1(VBAT_F) UNK13CS1.1 UNK13K10.3 UNK13K11.3 UNK13K12.3 UNK13TP_VBAT_F.1
S13_VBAT_K11C: UNK13C6.1 UNK13K11.4
S13_VBAT_K12: UNK13C9.1 UNK13K12.4 UNK13TP_REF_5V.1 UNK13U1.6
S13_VBAT_S: SITE13.S1(VBAT_S) UNK13K10.6 UNK13K12.6 UNK13TP_VBAT_S.1
S13_VBUS_CK: UNK13C2.2 UNK13K1.3
S13_VSET: SITE13.F8(VSET_F) SITE13.S8(VSET_S) UNK13K3.3 UNK13TP_VEST.1
S13_VSET_K3R: UNK13K3.2 UNK13R1.2
S14_AVSS_GS: UNK14R13.2 UNK14R14.2 UNK14RS1.1 UNK14RS2.1 UNK14RS5.1
S14_AVSS_S[01]: SITE14.S3(AVSS_S[01]) UNK14RS1.2 UNK14RS3.2
S14_EPAD2: SITE14.EPAD2(AVSS[02]) SITE14.G6 UNK14RS5.2
S14_NCHG / ATB0_F: SITE14.F26(NCHG / ATB0_F) UNK14CS26.2 UNK14K14.3
S14_NCHG / ATB0_S: SITE14.S26(NCHG / ATB0_S) UNK14K14.6 UNK14TP_NCHG/ATB0_S.1
S14_NPG / ATB1_F: SITE14.F27(NPG / ATB1_F) UNK14CS27.2 UNK14K13.3
S14_NPG / ATB1_S: SITE14.S27(NPG / ATB1_S) UNK14K13.6
S14_NTC: SITE14.F7(NTC_F) SITE14.S7(NTC_S) UNK14K4.3 UNK14TP_NTC.1
S14_NTC_K4K: UNK14K4.2 UNK14K5.3 UNK14K6.3 UNK14K7.3
S14_SCL: SITE14.F15(SCL_F) SITE14.S15(SCL_S) UNK14K9.6 UNK14SH40.2 UNK14TP_SCL.1
S14_SCL_K9R: UNK14K9.5 UNK14R7.2
S14_SDA: SITE14.F14(SDA_F) SITE14.S14(SDA_S) UNK14K9.3 UNK14SH41.2 UNK14TP_SDA.1
S14_SDA_K9R: UNK14K9.4 UNK14R8.2
S14_VBAT_F: SITE14.F1(VBAT_F) UNK14CS1.1 UNK14K10.3 UNK14K11.3 UNK14K12.3 UNK14TP_VBAT_F.1
S14_VBAT_K11C: UNK14C6.1 UNK14K11.4
S14_VBAT_K12: UNK14C9.1 UNK14K12.4 UNK14TP_REF_5V.1 UNK14U1.6
S14_VBAT_S: SITE14.S1(VBAT_S) UNK14K10.6 UNK14K12.6 UNK14TP_VBAT_S.1
S14_VBUS_CK: UNK14C2.2 UNK14K1.3
S14_VSET: SITE14.F8(VSET_F) SITE14.S8(VSET_S) UNK14K3.3 UNK14TP_VEST.1
S14_VSET_K3R: UNK14K3.2 UNK14R1.2
S15_AVSS_GS: UNK15R13.2 UNK15R14.2 UNK15RS1.1 UNK15RS2.1 UNK15RS5.1
S15_AVSS_S[01]: SITE15.S3(AVSS_S[01]) UNK15RS1.2 UNK15RS3.2
S15_EPAD2: SITE15.EPAD2(AVSS[02]) SITE15.G6 UNK15RS5.2
S15_NCHG / ATB0_F: SITE15.F26(NCHG / ATB0_F) UNK15CS26.2 UNK15K14.3
S15_NCHG / ATB0_S: SITE15.S26(NCHG / ATB0_S) UNK15K14.6 UNK15TP_NCHG/ATB0_S.1
S15_NPG / ATB1_F: SITE15.F27(NPG / ATB1_F) UNK15CS27.2 UNK15K13.3
S15_NPG / ATB1_S: SITE15.S27(NPG / ATB1_S) UNK15K13.6
S15_NTC: SITE15.F7(NTC_F) SITE15.S7(NTC_S) UNK15K4.3 UNK15TP_NTC.1
S15_NTC_K4K: UNK15K4.2 UNK15K5.3 UNK15K6.3 UNK15K7.3
S15_SCL: SITE15.F15(SCL_F) SITE15.S15(SCL_S) UNK15K9.6 UNK15SH40.2 UNK15TP_SCL.1
S15_SCL_K9R: UNK15K9.5 UNK15R7.2
S15_SDA: SITE15.F14(SDA_F) SITE15.S14(SDA_S) UNK15K9.3 UNK15SH41.2 UNK15TP_SDA.1
S15_SDA_K9R: UNK15K9.4 UNK15R8.2
S15_VBAT_F: SITE15.F1(VBAT_F) UNK15CS1.1 UNK15K10.3 UNK15K11.3 UNK15K12.3 UNK15TP_VBAT_F.1
S15_VBAT_K11C: UNK15C6.1 UNK15K11.4
S15_VBAT_K12: UNK15C9.1 UNK15K12.4 UNK15TP_REF_5V.1 UNK15U1.6
S15_VBAT_S: SITE15.S1(VBAT_S) UNK15K10.6 UNK15K12.6 UNK15TP_VBAT_S.1
S15_VBUS_CK: UNK15C2.2 UNK15K1.3
S15_VSET: SITE15.F8(VSET_F) SITE15.S8(VSET_S) UNK15K3.3 UNK15TP_VEST.1
S15_VSET_K3R: UNK15K3.2 UNK15R1.2
S16_AVSS_GS: UNK16R13.2 UNK16R14.2 UNK16RS1.1 UNK16RS2.1 UNK16RS5.1
S16_AVSS_S[01]: SITE16.S3(AVSS_S[01]) UNK16RS1.2 UNK16RS3.2
S16_EPAD2: SITE16.EPAD2(AVSS[02]) SITE16.G6 UNK16RS5.2
S16_NCHG / ATB0_F: SITE16.F26(NCHG / ATB0_F) UNK16CS26.2 UNK16K14.3
S16_NCHG / ATB0_S: SITE16.S26(NCHG / ATB0_S) UNK16K14.6 UNK16TP_NCHG/ATB0_S.1
S16_NPG / ATB1_F: SITE16.F27(NPG / ATB1_F) UNK16CS27.2 UNK16K13.3
S16_NPG / ATB1_S: SITE16.S27(NPG / ATB1_S) UNK16K13.6
S16_NTC: SITE16.F7(NTC_F) SITE16.S7(NTC_S) UNK16K4.3 UNK16TP_NTC.1
S16_NTC_K4K: UNK16K4.2 UNK16K5.3 UNK16K6.3 UNK16K7.3
S16_SCL: SITE16.F15(SCL_F) SITE16.S15(SCL_S) UNK16K9.6 UNK16SH40.2 UNK16TP_SCL.1
S16_SCL_K9R: UNK16K9.5 UNK16R7.2
S16_SDA: SITE16.F14(SDA_F) SITE16.S14(SDA_S) UNK16K9.3 UNK16SH41.2 UNK16TP_SDA.1
S16_SDA_K9R: UNK16K9.4 UNK16R8.2
